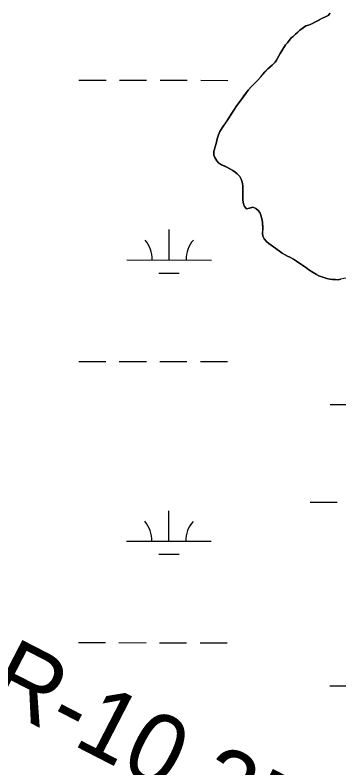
# Model space of a CAD drawing. Extents: x 3148686 to 3186545, y 916144 to 941516.
# Drawn here: x 3161200 to 3161583, y 927974 to 928865 of the extents above; entities that cross this region are included whole.
import ezdxf

# ---------------------------------------------------------------- set-up
doc = ezdxf.new("R2010")
doc.units = 0
for name, color, linetype in [('V-RIVR-RANG-IDEN', 7, 'Continuous'), ('V-SITE-VEGE', 7, 'Continuous'), ('V-TOPO-SHOR', 7, 'Continuous'), ('V-WETL-SWMP', 7, 'Continuous')]:
    doc.layers.add(name, color=color, linetype=linetype)

msp = doc.modelspace()

# ---------------------------------------------------------------- linework, layer by layer
at = {"layer": 'V-SITE-VEGE'}
msp.add_lwpolyline([(3161572.36, 928867.46), (3161569.78, 928864.65), (3161566.79, 928863.03), (3161563.79, 928862.01), (3161554.22, 928856.76), (3161550.63, 928854.54), (3161546.64, 928853.32), (3161543.64, 928852.5), (3161536.47, 928847.25), (3161533.89, 928845.04), (3161531.3, 928842.62), (3161528.51, 928839.81), (3161526.12, 928837.99), (3161521.76, 928832.37), (3161519.37, 928829.75), (3161513.23, 928819.51), (3161508.87, 928811.89), (3161507.09, 928809.48), (3161503.51, 928805.66), (3161498.33, 928801.42), (3161486.81, 928788.16), (3161479.25, 928780.51), (3161475.47, 928776.29), (3161473.29, 928773.67), (3161468.13, 928766.44), (3161461.78, 928758.21), (3161458.41, 928752.58), (3161452.06, 928742.74), (3161446.31, 928734.11), (3161441.95, 928727.28), (3161440.17, 928723.27), (3161438.6, 928718.86), (3161437.82, 928714.86), (3161434.69, 928703.64), (3161434.51, 928699.44), (3161435.93, 928696.64), (3161438.35, 928692.66), (3161440.36, 928690.27), (3161443.78, 928688.09), (3161450, 928685.32), (3161453.61, 928683.34), (3161457.22, 928681.16), (3161459.83, 928679.38), (3161462.45, 928677.19), (3161465.26, 928674.01), (3161467.08, 928671.02), (3161468.3, 928667.63), (3161468.93, 928663.03), (3161469.15, 928659.03), (3161468.8, 928650.82), (3161469.03, 928646.03), (3161469.85, 928641.63), (3161471.07, 928638.63), (3161473.49, 928635.85), (3161476.68, 928636.47), (3161480.88, 928637.89), (3161484.29, 928636.11), (3161487.1, 928633.73), (3161488.91, 928631.34), (3161490.13, 928628.55), (3161491.36, 928624.15), (3161492.18, 928620.16), (3161492.62, 928613.76), (3161492.26, 928607.15), (3161492.68, 928603.55), (3161494.1, 928600.56), (3161497.11, 928597.18), (3161499.53, 928594.99), (3161505.35, 928590.83), (3161507.96, 928588.84), (3161515.6, 928583.48), (3161521.82, 928579.92), (3161524.63, 928578.54), (3161528.84, 928576.16), (3161532.46, 928573.98), (3161538.68, 928569.62), (3161542.9, 928566.84), (3161547.11, 928563.86), (3161552.14, 928560.49), (3161556.15, 928558.12), (3161558.96, 928556.73), (3161563.57, 928554.96), (3161568.18, 928553.58), (3161571.99, 928552.6), (3161574.99, 928552.22), (3161578.59, 928552.24), (3161581.59, 928551.86), (3161584.99, 928552.48)], dxfattribs=at)
at = {"layer": 'V-TOPO-SHOR'}
for points in [[(3161531.3, 928842.62), (3161533.89, 928845.04), (3161536.47, 928847.25), (3161540.26, 928850.08), (3161543.64, 928852.5), (3161546.64, 928853.31), (3161550.63, 928854.54), (3161554.22, 928856.76), (3161557.21, 928858.38), (3161560.4, 928860.19), (3161563.79, 928862.01), (3161566.79, 928863.03), (3161569.78, 928864.65), (3161572.36, 928867.46)], [(3161584.99, 928552.48), (3161581.59, 928551.86), (3161578.59, 928552.24), (3161574.99, 928552.22), (3161571.99, 928552.6), (3161568.18, 928553.58), (3161563.57, 928554.96), (3161558.96, 928556.73), (3161556.15, 928558.12), (3161552.14, 928560.49), (3161547.12, 928563.86), (3161542.9, 928566.84), (3161538.68, 928569.62), (3161535.87, 928571.6), (3161532.46, 928573.98), (3161528.84, 928576.16), (3161524.63, 928578.54), (3161521.82, 928579.92), (3161518.41, 928581.9), (3161515.6, 928583.48), (3161512.18, 928585.87), (3161507.96, 928588.84), (3161505.35, 928590.83), (3161502.34, 928593.01), (3161499.53, 928594.99), (3161497.11, 928597.18), (3161494.1, 928600.56), (3161492.68, 928603.55), (3161492.26, 928607.15), (3161492.43, 928610.76), (3161492.62, 928613.76), (3161492.4, 928616.76), (3161492.18, 928620.16), (3161491.36, 928624.15), (3161490.13, 928628.55), (3161488.91, 928631.34), (3161487.1, 928633.73), (3161484.29, 928636.11), (3161480.88, 928637.89), (3161476.68, 928636.47), (3161473.49, 928635.85), (3161471.07, 928638.64), (3161469.85, 928641.63), (3161469.03, 928646.03), (3161468.8, 928650.82), (3161468.97, 928655.03), (3161469.15, 928659.03), (3161468.93, 928663.03), (3161468.3, 928667.63), (3161467.08, 928671.02), (3161465.26, 928674.01), (3161462.45, 928677.19), (3161459.83, 928679.38), (3161457.22, 928681.16), (3161453.61, 928683.34), (3161450, 928685.32), (3161446.79, 928686.71), (3161443.78, 928688.09), (3161440.36, 928690.27), (3161438.35, 928692.66), (3161435.93, 928696.64), (3161434.51, 928699.44), (3161434.69, 928703.64), (3161436.25, 928709.25), (3161437.82, 928714.86), (3161438.6, 928718.86), (3161440.17, 928723.27), (3161441.95, 928727.28), (3161444.13, 928730.7), (3161446.31, 928734.11), (3161448.49, 928737.32), (3161452.06, 928742.74), (3161455.23, 928747.76), (3161458.41, 928752.58), (3161461.78, 928758.21), (3161465.35, 928762.83), (3161468.13, 928766.44), (3161470.31, 928769.45), (3161473.29, 928773.67), (3161475.47, 928776.29), (3161479.25, 928780.51), (3161483.23, 928784.53), (3161486.81, 928788.16), (3161490.18, 928791.97), (3161492.77, 928794.99), (3161495.15, 928797.81), (3161498.33, 928801.42), (3161503.51, 928805.66), (3161507.09, 928809.48), (3161508.87, 928811.89), (3161511.64, 928816.7), (3161513.23, 928819.51), (3161515.01, 928822.52), (3161517.39, 928826.54), (3161519.37, 928829.75), (3161521.76, 928832.37), (3161526.12, 928837.99), (3161528.51, 928839.81), (3161531.3, 928842.62)]]:
    msp.add_lwpolyline(points, dxfattribs=at)
at = {"layer": 'V-WETL-SWMP'}
for p, q in [((3161275.27, 928788.04), (3161307.27, 928788.01)), ((3161323.27, 928787.99), (3161355.27, 928787.96)), ((3161371.27, 928787.94), (3161403.27, 928787.91)), ((3161419.27, 928787.89), (3161451.27, 928787.86)), ((3161381.89, 928575.33), (3161381.92, 928611.33)), ((3161331.89, 928575.38), (3161431.89, 928575.27)), ((3161369.87, 928559.91), (3161393.87, 928559.88)), ((3161274.92, 928455.37), (3161306.92, 928455.33)), ((3161322.92, 928455.32), (3161354.92, 928455.28)), ((3161370.92, 928455.27), (3161402.92, 928455.23)), ((3161418.92, 928455.22), (3161450.92, 928455.18)), ((3161572.18, 928404.31), (3161672.18, 928404.21)), ((3161548.65, 928288.9), (3161580.65, 928288.87)), ((3161381.54, 928242.65), (3161381.57, 928278.65)), ((3161331.54, 928242.7), (3161431.54, 928242.6)), ((3161369.52, 928227.23), (3161393.52, 928227.21)), ((3161274.57, 928122.69), (3161306.57, 928122.66)), ((3161322.57, 928122.64), (3161354.57, 928122.61)), ((3161370.57, 928122.59), (3161402.57, 928122.56)), ((3161418.57, 928122.54), (3161450.56, 928122.51)), ((3161571.83, 928071.64), (3161603.31, 928071.6))]:
    msp.add_line(p, q, dxfattribs=at)
for points in [[(3161512.18, 928585.87), (3161507.96, 928588.84), (3161505.35, 928590.83), (3161502.34, 928593.01), (3161499.53, 928594.99), (3161497.11, 928597.18), (3161494.09, 928600.56), (3161492.68, 928603.56), (3161492.26, 928607.15), (3161492.43, 928610.76), (3161492.62, 928613.76), (3161492.4, 928616.76), (3161492.18, 928620.16), (3161491.36, 928624.15), (3161490.13, 928628.55), (3161488.91, 928631.34), (3161487.1, 928633.73), (3161484.29, 928636.11), (3161480.88, 928637.89), (3161476.68, 928636.47), (3161473.49, 928635.85), (3161471.07, 928638.64), (3161469.85, 928641.63), (3161469.03, 928646.03), (3161468.8, 928650.83), (3161468.97, 928655.03), (3161469.15, 928659.03), (3161468.93, 928663.03), (3161468.3, 928667.63), (3161467.08, 928671.02), (3161465.26, 928674.01), (3161462.44, 928677.19), (3161459.83, 928679.38), (3161457.22, 928681.16), (3161453.61, 928683.34), (3161450, 928685.32), (3161446.79, 928686.7), (3161443.78, 928688.09), (3161440.36, 928690.27), (3161438.35, 928692.66), (3161435.93, 928696.64), (3161434.51, 928699.44), (3161434.69, 928703.64), (3161437.82, 928714.86), (3161438.6, 928718.86), (3161440.17, 928723.27), (3161441.95, 928727.28), (3161446.31, 928734.11), (3161448.49, 928737.32), (3161452.06, 928742.75), (3161455.23, 928747.76), (3161458.41, 928752.58), (3161461.78, 928758.2), (3161465.35, 928762.83), (3161468.13, 928766.44), (3161470.31, 928769.46), (3161473.29, 928773.67), (3161475.47, 928776.29), (3161479.25, 928780.51), (3161486.81, 928788.15), (3161490.18, 928791.98), (3161492.77, 928794.99), (3161495.15, 928797.8), (3161498.33, 928801.42), (3161503.51, 928805.65), (3161507.09, 928809.48), (3161508.87, 928811.89), (3161511.65, 928816.7), (3161513.23, 928819.51), (3161517.39, 928826.54), (3161519.37, 928829.75), (3161521.76, 928832.37), (3161526.12, 928837.99), (3161528.51, 928839.81), (3161531.3, 928842.62), (3161533.89, 928845.04), (3161536.47, 928847.25), (3161540.26, 928850.08), (3161543.64, 928852.5), (3161546.64, 928853.31), (3161550.63, 928854.54), (3161554.22, 928856.76), (3161557.21, 928858.38), (3161560.4, 928860.19), (3161563.79, 928862.01), (3161566.79, 928863.03), (3161569.78, 928864.65), (3161572.36, 928867.46)], [(3161591.98, 928553.92), (3161588.18, 928553.3), (3161584.99, 928552.48), (3161581.59, 928551.86), (3161578.59, 928552.24), (3161574.99, 928552.22), (3161571.99, 928552.61), (3161568.18, 928553.58), (3161563.57, 928554.96), (3161558.96, 928556.73), (3161556.15, 928558.12), (3161552.14, 928560.49), (3161547.12, 928563.86), (3161542.9, 928566.84), (3161538.68, 928569.62), (3161535.87, 928571.6), (3161532.46, 928573.98), (3161528.84, 928576.16), (3161524.63, 928578.54), (3161521.82, 928579.92), (3161518.41, 928581.9), (3161515.6, 928583.48), (3161512.18, 928585.87)]]:
    msp.add_lwpolyline(points, dxfattribs=at)
for centre, start, end in [((3161326.64, 928575.86), 359.16781, 40.71147), ((3161437.13, 928575.74), 139.1678, 180.71146), ((3161326.29, 928243.18), 359.16781, 40.71147), ((3161436.78, 928243.07), 139.1678, 180.71146)]:
    msp.add_arc(centre, 35.25, start, end, dxfattribs=at)

# ---------------------------------------------------------------- texts
at = {"layer": 'V-RIVR-RANG-IDEN'}
msp.add_text('R-10.2B', height=83, rotation=332.7554, dxfattribs=at).set_placement((3161162.24, 928056.16))

doc.saveas('drawing.dxf')
